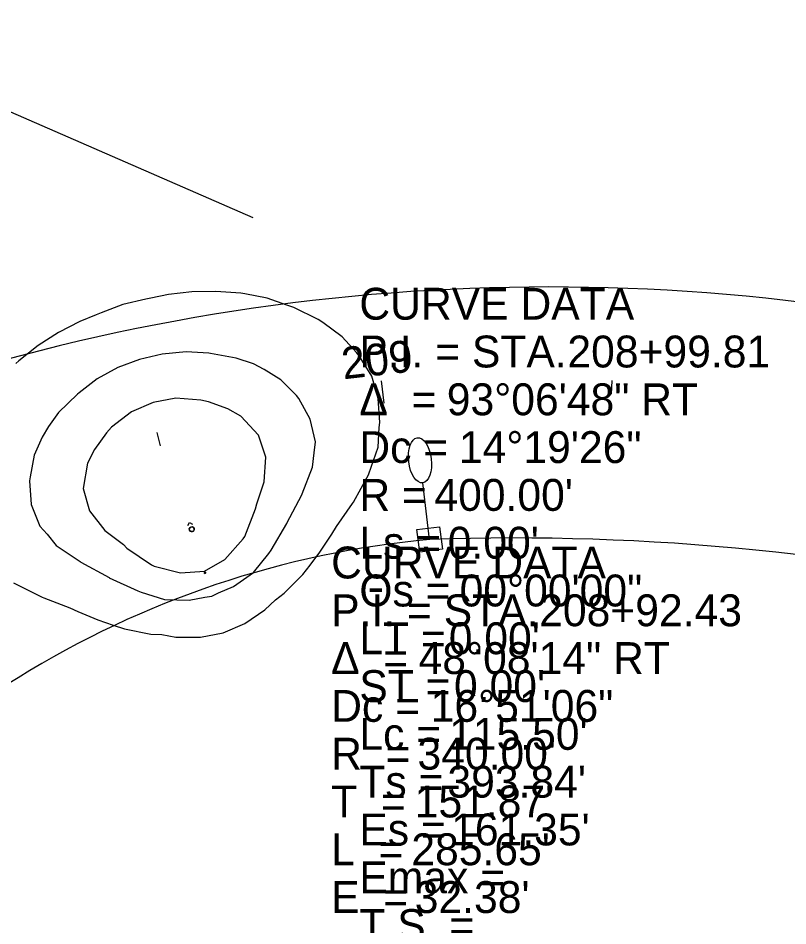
# Model space of a CAD drawing. Extents: x 1598538 to 1602183, y 285823 to 288192.
# Drawn here: x 1601192.8 to 1601361.7, y 286669.9 to 286869.3 of the extents above; entities that cross this region are included whole.
import ezdxf

# ---------------------------------------------------------------- set-up
doc = ezdxf.new("R2010")
doc.units = 0
for name, color, linetype in [('CM_Corridor_Conceptual', 7, 'Continuous'), ('Default', 7, 'Continuous'), ('MD_P_ACSC_B', 7, 'Continuous'), ('MD_P_AGB_B', 7, 'Continuous'), ('PV_P_Curb', 7, 'Continuous'), ('RW_P_Esmt_LA', 7, 'Continuous'), ('RW_P_Esmt_TMP', 7, 'Continuous')]:
    doc.layers.add(name, color=color, linetype=linetype)

msp = doc.modelspace()

# ---------------------------------------------------------------- linework, layer by layer
at = {"layer": 'Default'}
for points in [[(1601191.8, 286745.27), (1601198.05, 286742.05), (1601198.42, 286741.93), (1601204.17, 286739.74), (1601205.92, 286738.93), (1601210.3, 286737.11), (1601213.67, 286735.96), (1601216.17, 286735.11), (1601221.92, 286733.96), (1601224.3, 286733.86), (1601227.42, 286733.33), (1601232.8, 286733.33), (1601237.8, 286734.27), (1601242.55, 286736.3), (1601246.92, 286739.3), (1601249.3, 286741.49), (1601251.17, 286742.93), (1601255.3, 286747.05), (1601256.92, 286749.15), (1601259.05, 286751.99), (1601261.67, 286755.93), (1601262.67, 286757.61), (1601266.17, 286762.68), (1601266.42, 286762.93), (1601269.8, 286769.08), (1601269.8, 286769.15), (1601271.8, 286775.02), (1601272.05, 286779.33), (1601272.17, 286780.49), (1601271.8, 286785.71), (1601270.42, 286790.61), (1601267.67, 286795.11), (1601267.05, 286795.83), (1601263.92, 286799.3), (1601259.67, 286802.43), (1601258.67, 286803.05), (1601253.3, 286805.71), (1601251.8, 286806.27), (1601247.42, 286807.74), (1601242.55, 286808.74), (1601241.67, 286808.9), (1601236.17, 286809.27), (1601230.92, 286809.18), (1601225.8, 286808.58), (1601221.92, 286807.77), (1601220.8, 286807.58), (1601215.8, 286806.36), (1601211.05, 286804.58), (1601209.92, 286804.11), (1601206.3, 286802.61), (1601201.67, 286800.24), (1601197.17, 286797.36), (1601192.92, 286794.02), (1601192.3, 286793.4)], [(1601230.05, 286757.86), (1601230.42, 286758.52), (1601231.05, 286758.15)], [(1601230.55, 286757.36), (1601230.3, 286757.11), (1601230.3, 286757.11), (1601230.55, 286757.36), (1601230.55, 286757.36)], [(1601230.67, 286757.49), (1601230.55, 286757.36), (1601230.55, 286757.36), (1601230.67, 286757.49), (1601230.67, 286757.49)], [(1601230.3, 286757.11), (1601230.42, 286756.83), (1601230.42, 286756.83), (1601230.3, 286757.11), (1601230.3, 286757.11)]]:
    msp.add_lwpolyline(points, dxfattribs=at)
for points in [[(1601254.42, 286785.74), (1601253.92, 286786.36), (1601250.42, 286789.86), (1601246.8, 286792.11), (1601244.42, 286793.33), (1601240.67, 286794.61), (1601235.05, 286795.65), (1601234.67, 286795.68), (1601229.67, 286795.96), (1601224.42, 286795.49), (1601219.42, 286794.3), (1601214.67, 286792.52), (1601210.17, 286790.02), (1601206.17, 286786.99), (1601205.8, 286786.71), (1601201.67, 286782.68), (1601199.42, 286779.58), (1601198.05, 286777.21), (1601196.3, 286773.27), (1601195.42, 286768.49), (1601195.3, 286767.65), (1601195.67, 286762.46), (1601197.55, 286757.71), (1601199.17, 286755.9), (1601201.17, 286753.46), (1601206.42, 286749.9), (1601206.55, 286749.77), (1601212.8, 286746.4), (1601212.8, 286746.36), (1601219.05, 286743.46), (1601219.8, 286743.15), (1601224.92, 286741.55), (1601230.3, 286741.46), (1601233.8, 286742.08), (1601235.3, 286742.3), (1601236.8, 286743.02), (1601240.05, 286744.43), (1601244.42, 286747.49), (1601247.8, 286751.71), (1601248.3, 286752.4), (1601251.8, 286758.24), (1601251.8, 286758.33), (1601255.05, 286764.58), (1601255.17, 286764.8), (1601257.42, 286770.68), (1601257.8, 286773.8), (1601258.05, 286776.18), (1601256.92, 286781.18)], [(1601241.67, 286781.83), (1601238.8, 286783.43), (1601234.55, 286784.99), (1601232.92, 286785.4), (1601227.42, 286785.8), (1601222.42, 286784.86), (1601217.67, 286782.8), (1601213.3, 286779.43), (1601212.17, 286778.18), (1601209.55, 286774.49), (1601208.05, 286771.55), (1601207.05, 286765.93), (1601208.42, 286761.02), (1601211.8, 286756.71), (1601215.92, 286753.68), (1601216.67, 286752.86), (1601222.05, 286749.18), (1601222.67, 286748.93), (1601228.42, 286747.4), (1601233.67, 286747.83), (1601238.17, 286750.36), (1601242.17, 286754.9), (1601242.55, 286755.43), (1601244.92, 286761.49), (1601245.17, 286762.61), (1601246.8, 286767.4), (1601247.17, 286772.86), (1601245.55, 286777.68)], [(1601230.55, 286756.61), (1601230.8, 286756.49), (1601231.05, 286756.49), (1601231.3, 286756.61), (1601231.42, 286756.86), (1601231.42, 286757.15), (1601231.3, 286757.36), (1601231.05, 286757.52), (1601230.67, 286757.49), (1601230.55, 286757.36), (1601230.3, 286757.11), (1601230.42, 286756.83)], [(1601230.55, 286756.61), (1601230.8, 286756.49), (1601231.05, 286756.49), (1601231.3, 286756.61), (1601231.42, 286756.86), (1601231.42, 286757.15), (1601231.3, 286757.36), (1601231.05, 286757.52), (1601230.67, 286757.49), (1601230.55, 286757.36), (1601230.3, 286757.11), (1601230.42, 286756.83)], [(1601231.05, 286757.52), (1601230.67, 286757.49), (1601230.67, 286757.49), (1601231.05, 286757.52)], [(1601231.3, 286757.36), (1601231.05, 286757.52), (1601231.05, 286757.52), (1601231.3, 286757.36)], [(1601231.42, 286757.15), (1601231.3, 286757.36), (1601231.3, 286757.36), (1601231.42, 286757.15)], [(1601230.42, 286756.83), (1601230.55, 286756.61), (1601230.55, 286756.61), (1601230.42, 286756.83)], [(1601230.55, 286756.61), (1601230.8, 286756.49), (1601230.8, 286756.49), (1601230.55, 286756.61)], [(1601230.8, 286756.49), (1601231.05, 286756.49), (1601231.05, 286756.49), (1601230.8, 286756.49)], [(1601231.05, 286756.49), (1601231.3, 286756.61), (1601231.3, 286756.61), (1601231.05, 286756.49)], [(1601231.3, 286756.61), (1601231.42, 286756.86), (1601231.42, 286756.86), (1601231.3, 286756.61)], [(1601231.42, 286756.86), (1601231.42, 286757.15), (1601231.42, 286757.15), (1601231.42, 286756.86)], [(1601233.67, 286747.27), (1601233.92, 286747.33), (1601233.92, 286747.58), (1601233.67, 286747.52)], [(1601233.67, 286747.27), (1601233.92, 286747.33), (1601233.92, 286747.58), (1601233.67, 286747.52)], [(1601233.92, 286747.58), (1601233.67, 286747.52), (1601233.67, 286747.52), (1601233.92, 286747.58)], [(1601233.67, 286747.52), (1601233.67, 286747.27), (1601233.67, 286747.27), (1601233.67, 286747.52)], [(1601233.67, 286747.27), (1601233.92, 286747.33), (1601233.92, 286747.33), (1601233.67, 286747.27)], [(1601233.92, 286747.33), (1601233.92, 286747.58), (1601233.92, 286747.58), (1601233.92, 286747.33)]]:
    msp.add_lwpolyline(points, close=True, dxfattribs=at)
at = {"layer": 'MD_P_ACSC_B'}
msp.add_line((1600591.71, 287110.09), (1601244.34, 286825.47), dxfattribs=at)
at = {"layer": 'MD_P_AGB_B'}
for p, q in [((1601273.15, 286784.67), (1601272.58, 286789.63)), ((1601323.06, 286786.69), (1601323.16, 286789.69)), ((1601224.07, 286775.34), (1601223.3, 286778.24))]:
    msp.add_line(p, q, dxfattribs=at)
at = {"layer": 'RW_P_Esmt_LA'}
msp.add_line((1601283.12, 286754.78), (1601281.61, 286767.18), dxfattribs=at)
msp.add_lwpolyline([(1601280.94, 286751.99), (1601280.34, 286756.96), (1601285.3, 286757.56), (1601285.91, 286752.6)], close=True, dxfattribs=at)
msp.add_ellipse((1601281, 286772.15), major_axis=(-0.61, 4.96), ratio=0.5, dxfattribs=at)
at = {"layer": 'RW_P_Esmt_TMP'}
msp.add_line((1601192.79, 286724.4), (1601157.48, 286703.15), dxfattribs=at)
for centre, radius, start, end in [((1601309.46, 286355.9), 454.33, 73.5556, 108.674), ((1601302.47, 286547.77), 207.91, 95.338, 121.8368), ((1601301.47, 286221.46), 533.63, 76.5827, 91.9701)]:
    msp.add_arc(centre, radius, start, end, dxfattribs=at)

# ---------------------------------------------------------------- texts
at = {"layer": 'CM_Corridor_Conceptual'}
for s, p in [('CURVE DATA', (1601267.69, 286803.05)), ('P.I. = STA. ', (1601267.69, 286792.55)), ('208+99.81', (1601313.36, 286792.55)), ('93°06\'48" RT', (1601286.88, 286782.05)), ('Δ  = ', (1601267.69, 286782.05)), ('Dc = ', (1601267.69, 286771.55)), ('14°19\'26"', (1601289.54, 286771.55)), ('R = ', (1601267.69, 286761.05)), ("400.00'", (1601284.16, 286761.05)), ('Ls = ', (1601267.69, 286750.55)), ("0.00'", (1601287.09, 286750.55)), ('CURVE DATA', (1601261.5, 286746.2)), ('Θs = ', (1601267.69, 286740.05)), ('00°00\'00"', (1601289.7, 286740.05)), ('P.I. = STA. ', (1601261.5, 286735.7)), ('208+92.43', (1601307.17, 286735.7)), ('LT = ', (1601267.69, 286729.55)), ("0.00'", (1601287.32, 286729.55)), ('Δ  = ', (1601261.5, 286725.2)), ('48°08\'14" RT', (1601280.69, 286725.2)), ('ST = ', (1601267.69, 286719.05)), ("0.00'", (1601288.46, 286719.05)), ('Dc = ', (1601261.5, 286714.7)), ('16°51\'06"', (1601283.35, 286714.7)), ('Lc = ', (1601267.69, 286708.55)), ("115.50'", (1601287.39, 286708.55)), ('R  = ', (1601261.5, 286704.2)), ("340.00'", (1601280.45, 286704.2)), ('Ts = ', (1601267.69, 286698.05)), ("393.84'", (1601287.03, 286698.05)), ('T  = ', (1601261.5, 286693.7)), ("151.87'", (1601279.84, 286693.7)), ('Es = ', (1601267.69, 286687.55)), ("161.35'", (1601287.84, 286687.55)), ('L  = ', (1601261.5, 286683.2)), ("285.65'", (1601279.1, 286683.2)), ('Emax = ', (1601267.69, 286677.05)), ('E  = ', (1601261.5, 286672.7)), ("32.38'", (1601279.85, 286672.7)), ('T.S. = ', (1601267.69, 286666.55))]:
    msp.add_text(s, height=7, dxfattribs=at).set_placement(p)
at = {"layer": 'MD_P_AGB_B'}
msp.add_text('209', height=7, rotation=6.5413, dxfattribs=at).set_placement((1601264.19, 286789.93))
at = {"layer": 'PV_P_Curb'}
msp.add_text('207+40.57', height=7, rotation=303.4087, dxfattribs=at).set_placement((1601164.2, 286670.96))

doc.saveas('drawing.dxf')
